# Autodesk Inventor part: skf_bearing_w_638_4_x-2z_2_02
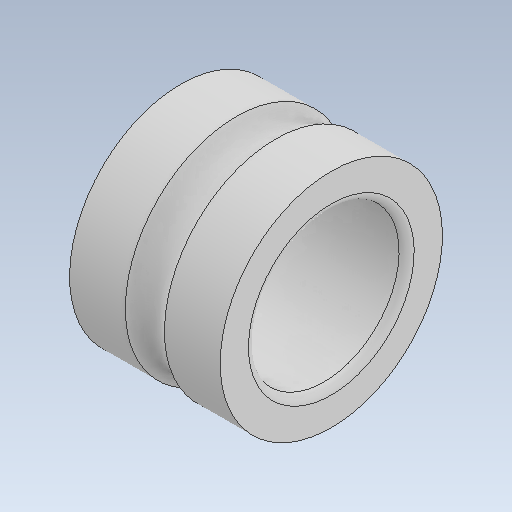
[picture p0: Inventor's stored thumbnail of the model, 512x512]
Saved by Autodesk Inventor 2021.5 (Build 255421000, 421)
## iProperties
Created: 2023-12
Part Number: skf_bearing_w_638_4_x-2z_2_02
Checked By: TraceParts S.A.
Material: Generic
Catalog Web Link: www.traceparts.com
Document SubType Name: Modeling
Designer: TraceParts
Density: 1 g/cm^3
Appearance: Default
Company: TraceParts S.A.
Author: TraceParts
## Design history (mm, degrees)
feature "skf_bearing_w_638_4_x-2z_2_02.ipt"
body "Solid1"
